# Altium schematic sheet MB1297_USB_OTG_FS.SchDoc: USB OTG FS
size A4; Date: Not used; ApprovedBy: Not used; CheckedBy: Not used; Author: Not used; CompanyName: STMicroelectronics; DrawnBy: Not used; Engineer: Not used; Organization: Not used; Address1: Not used; Address2: Not used; Address3: Not used; Address4: Not used; DocumentNumber: Not used; Revision: Not used; SheetNumber: 5; SheetTotal: 12
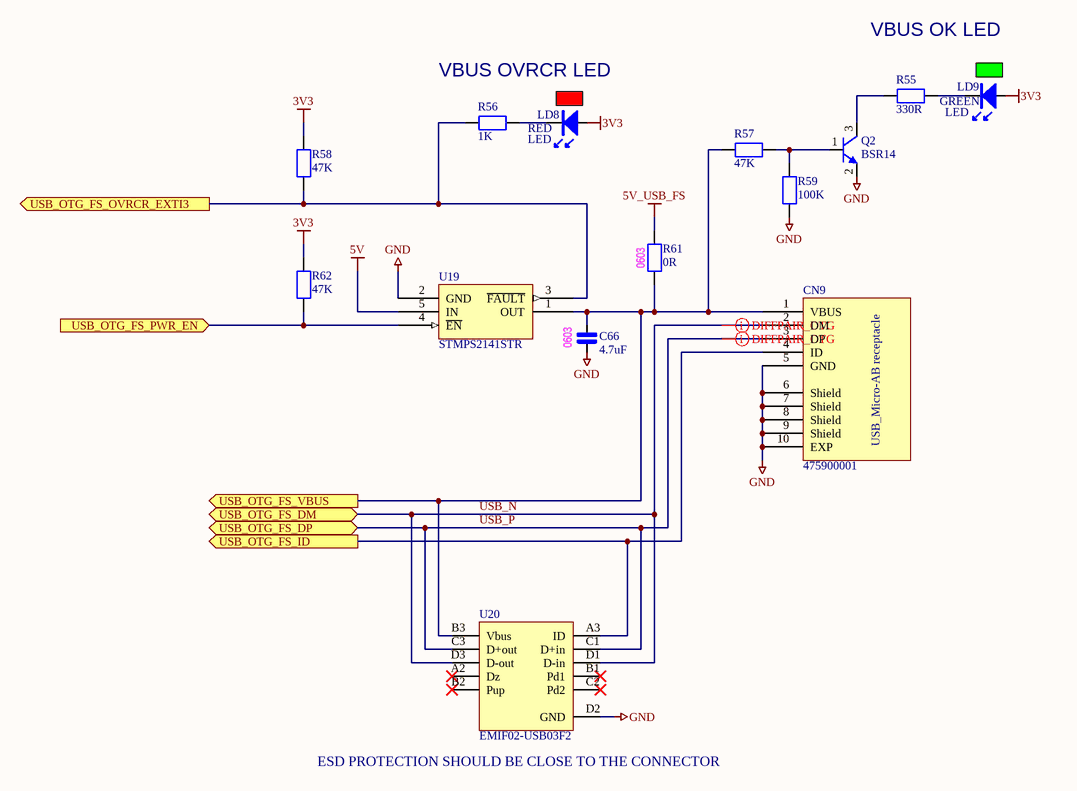
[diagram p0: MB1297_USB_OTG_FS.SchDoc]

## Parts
C66  4.7uF  [0603_CAP_NPOL]
CN9  475900001  [CON_USBMICROAB_MOLEX_47590-0001_H3]
LD8  LED  Color: RED  [0603_LED_RED]
LD9  LED  Color: GREEN  [0603_LED_GREEN]
Q2  BSR14  [SOT23-3]
R55  330R  [0402]
R56  1K  [0402]
R57  47K  [0402]
R58  47K  [0402]
R59  100K  [0402]
R61  0R  [0603_RES]
R62  47K  [0402]
U19  STMPS2141STR  [MOS_SOT23-5L]
U20  EMIF02-USB03F2  [ESD_FLIP-CHIP-BGA11_1P44X1P94_P050]

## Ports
USB_OTG_FS_DM (bidir), USB_OTG_FS_DP (bidir), USB_OTG_FS_ID (out), USB_OTG_FS_OVRCR_EXTI3 (out), USB_OTG_FS_PWR_EN (in), USB_OTG_FS_VBUS (out)

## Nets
3V3: LD8.A LD9.A R58.1 R62.1
5V: U19.5(IN)
5V_USB_FS: R61.1
GND: C66.2 CN9.5(GND) CN9.6(Shield) CN9.7(Shield) CN9.8(Shield) CN9.9(Shield) CN9.10(EXP) Q2.2(E) R59.1 U19.2(GND) U20.D2(GND)
USB_N: CN9.2(DM) U20.D1(D-in) U20.D3(D-out) ; port USB_OTG_FS_DM
USB_OTG_FS_ID: CN9.4(ID) U20.A3(ID) ; port USB_OTG_FS_ID
USB_OTG_FS_OVRCR_EXTI3: R56.1 R58.2 U19.3(~{FAULT}) ; port USB_OTG_FS_OVRCR_EXTI3
USB_OTG_FS_PWR_EN: R62.2 U19.4(~{EN}) ; port USB_OTG_FS_PWR_EN
USB_OTG_FS_VBUS: C66.1 CN9.1(VBUS) R57.1 R61.2 U19.1(OUT) U20.B3(Vbus) ; port USB_OTG_FS_VBUS
USB_P: CN9.3(DP) U20.C1(D+in) U20.C3(D+out) ; port USB_OTG_FS_DP
NetLD8_K: LD8.K R56.2
NetLD9_K: LD9.K R55.2
NetQ2_1: Q2.1(B) R57.2 R59.2
NetQ2_3: Q2.3(C) R55.1

Not connected (* = marked no-connect by the designer): U20 A2(Dz)* B1(Pd1)* B2(Pup)* C2(Pd2)*

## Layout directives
differential pair: USB_N, USB_P

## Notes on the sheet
- VBUS OVRCR LED
- VBUS OK LED
- (near R61) 0603
- (near C66) 0603
- (near U20) ESD PROTECTION SHOULD BE CLOSE TO THE CONNECTOR

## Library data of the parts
C66 = CAP_NPOL: Capacitor_not polarized
CN9 = 475900001: USB-MICRO-AB, 47590-0001, SMT, MOLEX; Fitted: YES; Ordered_By: Subcon
LD8 LD9 = LED: Light-Emitting Diode
Q2 = BSR14: BSR14 NPN switching transistor SOT23 (Marking U8)
R55-R59 R61 R62 = RES: Resistor
U19 = STMPS2141STR: Enhanced single channel power switches; Manuf_1: STM; ECCN_US/EU: EAR99/NEC; Ref St: 9159003; Fitted: YES
U20 = EMIF02-USB03F2: 2-line IPAD, EMI filter including ESD protection; Manuf_1: STM; ECCN_US/EU: EAR99/NEC; Fitted: YES; REF_STM: 9179037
